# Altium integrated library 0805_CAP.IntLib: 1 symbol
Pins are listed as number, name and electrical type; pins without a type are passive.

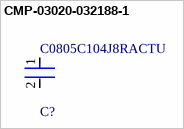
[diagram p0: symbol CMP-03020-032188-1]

## CMP-03020-032188-1
designator C?, comment C0805C104J8RACTU
CAP CER 0.1UF 10V 5% X7R 0805; Manufacturer: KEMET; Material: Ceramic; Tolerance: 0.05; Capacitance: 0.10 μF; Temperature Coefficient: 30ppm/°C; Value: 0.10 μF
footprint FP-C0805C-DN-IPC_A
footprint FP-C0805C-DN-IPC_C
footprint FP-C0805C-DN-MFG
footprint FP-C0805C-DN-IPC_B
pins: 1, 2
